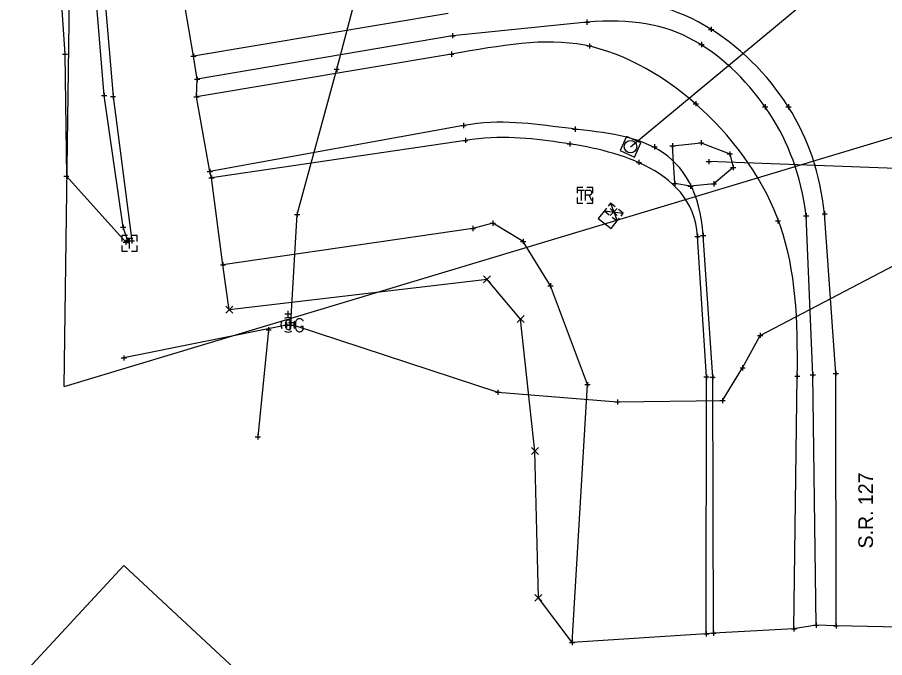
# Model space of a CAD drawing. Extents: x 1391912 to 1392597, y 304167 to 305226.
# Drawn here: x 1392156.2 to 1392322.5, y 304318.9 to 304441.7 of the extents above; entities that cross this region are included whole.
import ezdxf

# ---------------------------------------------------------------- set-up
doc = ezdxf.new("R2010")
doc.units = 0
for name, color, linetype in [('BD_X_Building', 7, 'Continuous'), ('DR_X_Erosion_Control', 7, 'Continuous'), ('DR_X_Storm_Sewer', 7, 'Continuous'), ('DV_X_Section_VMS_Line', 7, 'Continuous'), ('PM_X_Edge_Line', 7, 'Continuous'), ('PV_X_EOP', 7, 'Continuous'), ('PV_X_Shoulder_Aggregate', 7, 'Continuous'), ('RW_X_CL_100_Cardinal_Points', 7, 'Continuous'), ('RW_X_Esmt_SH', 7, 'Continuous'), ('SC_Scratch6', 7, 'Continuous'), ('SG_X_Controllers', 7, 'Continuous'), ('SG_X_Messenger_Wire', 7, 'Continuous'), ('SV_X_Break_Lines', 7, 'Continuous'), ('SV_X_Terrain_Boundary', 7, 'Continuous'), ('SV_X_Text', 7, 'Continuous'), ('SV_X_Toe_of_Slope', 7, 'Continuous'), ('SV_X_Top_of_Bank', 7, 'Continuous'), ('UT_X_FO', 7, 'Continuous'), ('UT_X_Gas', 7, 'Continuous'), ('UT_X_Gas_Cells', 7, 'Continuous'), ('UT_X_Overhead_Combined', 7, 'Continuous'), ('UT_X_Telecom_Cells', 7, 'Continuous')]:
    doc.layers.add(name, color=color, linetype=linetype)

msp = doc.modelspace()

# ---------------------------------------------------------------- linework, layer by layer
at = {"layer": 'BD_X_Building'}
for p, q in [((1392146.35, 304303.93), (1392176.61, 304336.54)), ((1392176.61, 304336.54), (1392223.75, 304292.79))]:
    msp.add_line(p, q, dxfattribs=at)
at = {"layer": 'DR_X_Erosion_Control'}
msp.add_lwpolyline([(1392281.81, 304417.04), (1392287.29, 304417.63), (1392292.82, 304415.47), (1392293.46, 304412.88), (1392289.75, 304409.75), (1392285.29, 304409.31), (1392282.24, 304409.83)], close=True, dxfattribs=at)
msp.add_lwpolyline([(1392281.81, 304417.04), (1392287.29, 304417.63), (1392292.82, 304415.47), (1392293.46, 304412.88), (1392289.75, 304409.75), (1392285.29, 304409.31), (1392282.24, 304409.83)], close=True, dxfattribs=at)
at = {"layer": 'DR_X_Storm_Sewer'}
msp.add_line((1392393.06, 304410.21), (1392288.79, 304414), dxfattribs=at)
at = {"layer": 'DV_X_Section_VMS_Line'}
for p, q in [((1392269.9, 304403.66), (1392271.23, 304405)), ((1392269.9, 304405), (1392271.23, 304403.66)), ((1392245.61, 304390.73), (1392246.94, 304392.07)), ((1392245.61, 304392.07), (1392246.94, 304390.73)), ((1392196.17, 304384.92), (1392197.5, 304386.26)), ((1392196.17, 304386.26), (1392197.5, 304384.92)), ((1392252.03, 304383.15), (1392253.37, 304384.49)), ((1392252.03, 304384.49), (1392253.37, 304383.15)), ((1392254.78, 304357.84), (1392256.11, 304359.18)), ((1392254.78, 304359.18), (1392256.11, 304357.84)), ((1392255.45, 304329.69), (1392256.78, 304331.02)), ((1392255.45, 304331.02), (1392256.78, 304329.69))]:
    msp.add_line(p, q, dxfattribs=at)
at = {"layer": 'PM_X_Edge_Line'}
for p, q in [((1392238.83, 304442.38), (1392189.99, 304434.24)), ((1392313.12, 304373.36), (1392310.98, 304404.01)), ((1392313.17, 304324.96), (1392313.12, 304373.36))]:
    msp.add_line(p, q, dxfattribs=at)
msp.add_open_spline([(1392310.98, 304404.01), (1392310.09, 304411.72), (1392305.75, 304424.92), (1392288.84, 304442.14), (1392274.13, 304445.52), (1392264.78, 304445.4)], degree=3, dxfattribs=at)
at = {"layer": 'PV_X_EOP'}
for p, q in [((1392265.4, 304440.73), (1392239.63, 304438.15)), ((1392239.63, 304438.15), (1392190.68, 304429.78)), ((1392308.72, 304373.11), (1392307.46, 304403.62)), ((1392309.33, 304325.11), (1392308.72, 304373.11))]:
    msp.add_line(p, q, dxfattribs=at)
msp.add_open_spline([(1392307.46, 304403.62), (1392306.37, 304411.58), (1392301.86, 304423.53), (1392286.65, 304439.27), (1392273.86, 304441.45), (1392265.4, 304440.73)], degree=3, dxfattribs=at)
at = {"layer": 'PV_X_Shoulder_Aggregate'}
for p, q in [((1392239.42, 304434.62), (1392190.55, 304426.44)), ((1392305.1, 304324.39), (1392305.74, 304372.84))]:
    msp.add_line(p, q, dxfattribs=at)
msp.add_open_spline([(1392305.74, 304372.84), (1392305.89, 304383.75), (1392305.02, 304402.43), (1392288.72, 304425.47), (1392264.99, 304439.43), (1392249.14, 304436.25), (1392239.42, 304434.62)], degree=3, dxfattribs=at)
at = {"layer": 'RW_X_CL_100_Cardinal_Points'}
msp.add_line((1392265.02, 304407.54), (1392265.02, 304407.54), dxfattribs=at)
for points in [[(1392264.62, 304409.04), (1392263.52, 304409.04), (1392263.52, 304407.94)], [(1392263.66, 304408.54), (1392264.91, 304408.54)], [(1392264.29, 304408.54), (1392264.29, 304406.54)], [(1392265.13, 304406.54), (1392265.13, 304408.54), (1392265.89, 304408.54), (1392265.97, 304408.53), (1392266.08, 304408.5), (1392266.12, 304408.46), (1392266.17, 304408.43), (1392266.24, 304408.35), (1392266.28, 304408.28), (1392266.31, 304408.15), (1392266.31, 304407.96), (1392266.3, 304407.9), (1392266.27, 304407.8), (1392266.2, 304407.69), (1392266.14, 304407.65), (1392266.09, 304407.61), (1392266.06, 304407.6), (1392266.01, 304407.58), (1392265.87, 304407.57), (1392265.13, 304407.57)], [(1392266.52, 304407.94), (1392266.52, 304409.04), (1392265.42, 304409.04)], [(1392263.52, 304407.14), (1392263.52, 304406.04), (1392264.62, 304406.04)], [(1392265.42, 304406.04), (1392266.52, 304406.04), (1392266.52, 304407.14)], [(1392265.87, 304407.57), (1392266.31, 304406.54)]]:
    msp.add_lwpolyline(points, dxfattribs=at)
at = {"layer": 'RW_X_Esmt_SH'}
for p, q in [((1392264.9, 304440.73), (1392265.9, 304440.73)), ((1392265.4, 304441.23), (1392265.4, 304440.23)), ((1392265.4, 304440.73), (1392265.4, 304440.73)), ((1392289.22, 304439.86), (1392289.22, 304438.86)), ((1392239.13, 304438.15), (1392240.13, 304438.15)), ((1392239.63, 304438.65), (1392239.63, 304437.65)), ((1392239.63, 304438.15), (1392239.63, 304438.15)), ((1392288.72, 304439.36), (1392289.72, 304439.36)), ((1392289.22, 304439.36), (1392289.22, 304439.36)), ((1392265.88, 304436.68), (1392265.88, 304435.68)), ((1392287.39, 304436.94), (1392287.39, 304435.94)), ((1392165.35, 304435.1), (1392165.35, 304434.1)), ((1392239.42, 304435.12), (1392239.42, 304434.12)), ((1392265.38, 304436.18), (1392266.38, 304436.18)), ((1392265.88, 304436.18), (1392265.88, 304436.18)), ((1392286.89, 304436.44), (1392287.89, 304436.44)), ((1392287.39, 304436.44), (1392287.39, 304436.44)), ((1392164.85, 304434.6), (1392165.85, 304434.6)), ((1392165.35, 304434.6), (1392165.35, 304434.6)), ((1392189.49, 304434.24), (1392190.49, 304434.24)), ((1392189.99, 304434.74), (1392189.99, 304433.74)), ((1392189.99, 304434.24), (1392189.99, 304434.24)), ((1392238.92, 304434.62), (1392239.92, 304434.62)), ((1392239.42, 304434.62), (1392239.42, 304434.62)), ((1392216.94, 304431.72), (1392217.94, 304431.72)), ((1392217.44, 304432.22), (1392217.44, 304431.22)), ((1392217.44, 304431.72), (1392217.44, 304431.72)), ((1392190.68, 304430.28), (1392190.68, 304429.28)), ((1392190.18, 304429.78), (1392191.18, 304429.78)), ((1392190.68, 304429.78), (1392190.68, 304429.78)), ((1392172.38, 304426.71), (1392173.38, 304426.71)), ((1392172.88, 304427.21), (1392172.88, 304426.21)), ((1392172.88, 304426.71), (1392172.88, 304426.71)), ((1392174.56, 304426.97), (1392174.56, 304425.97)), ((1392190.55, 304426.94), (1392190.55, 304425.94)), ((1392174.06, 304426.47), (1392175.06, 304426.47)), ((1392174.56, 304426.47), (1392174.56, 304426.47)), ((1392190.05, 304426.44), (1392191.05, 304426.44)), ((1392190.55, 304426.44), (1392190.55, 304426.44)), ((1392285.8, 304425.11), (1392286.8, 304425.11)), ((1392286.3, 304425.61), (1392286.3, 304424.61)), ((1392286.3, 304425.11), (1392286.3, 304425.11)), ((1392299.59, 304425.01), (1392299.59, 304424.01)), ((1392304.07, 304425), (1392304.07, 304424)), ((1392299.09, 304424.51), (1392300.09, 304424.51)), ((1392299.59, 304424.51), (1392299.59, 304424.51)), ((1392303.57, 304424.5), (1392304.57, 304424.5)), ((1392304.07, 304424.5), (1392304.07, 304424.5)), ((1392241.25, 304420.92), (1392242.25, 304420.92)), ((1392241.75, 304421.42), (1392241.75, 304420.42)), ((1392241.75, 304420.92), (1392241.75, 304420.92)), ((1392262.67, 304420.24), (1392263.67, 304420.24)), ((1392263.17, 304420.74), (1392263.17, 304419.74)), ((1392263.17, 304420.24), (1392263.17, 304420.24)), ((1392242.11, 304418.58), (1392242.11, 304417.58)), ((1392241.61, 304418.08), (1392242.61, 304418.08)), ((1392242.11, 304418.08), (1392242.11, 304418.08)), ((1392261.64, 304417.39), (1392262.64, 304417.39)), ((1392262.14, 304417.89), (1392262.14, 304416.89)), ((1392262.14, 304417.39), (1392262.14, 304417.39)), ((1392277.86, 304416.84), (1392278.86, 304416.84)), ((1392278.36, 304417.34), (1392278.36, 304416.34)), ((1392278.36, 304416.84), (1392278.36, 304416.84)), ((1392281.31, 304417.04), (1392282.31, 304417.04)), ((1392281.81, 304417.54), (1392281.81, 304416.54)), ((1392281.81, 304417.04), (1392281.81, 304417.04)), ((1392286.79, 304417.63), (1392287.79, 304417.63)), ((1392287.29, 304418.13), (1392287.29, 304417.13)), ((1392287.29, 304417.63), (1392287.29, 304417.63)), ((1392292.32, 304415.47), (1392293.32, 304415.47)), ((1392292.82, 304415.97), (1392292.82, 304414.97)), ((1392292.82, 304415.47), (1392292.82, 304415.47)), ((1392274.89, 304413.86), (1392275.89, 304413.86)), ((1392275.39, 304414.36), (1392275.39, 304413.36)), ((1392275.39, 304413.86), (1392275.39, 304413.86)), ((1392288.29, 304414), (1392289.29, 304414)), ((1392288.79, 304414.5), (1392288.79, 304413.5)), ((1392288.79, 304414), (1392288.79, 304414)), ((1392293.46, 304413.38), (1392293.46, 304412.38)), ((1392165.62, 304411.68), (1392165.62, 304410.68)), ((1392192.63, 304412.11), (1392193.63, 304412.11)), ((1392193.13, 304412.61), (1392193.13, 304411.61)), ((1392193.13, 304412.11), (1392193.13, 304412.11)), ((1392292.96, 304412.88), (1392293.96, 304412.88)), ((1392293.46, 304412.88), (1392293.46, 304412.88)), ((1392165.12, 304411.18), (1392166.12, 304411.18)), ((1392165.62, 304411.18), (1392165.62, 304411.18)), ((1392192.94, 304410.87), (1392193.94, 304410.87)), ((1392193.44, 304411.37), (1392193.44, 304410.37)), ((1392193.44, 304410.87), (1392193.44, 304410.87)), ((1392282.24, 304410.33), (1392282.24, 304409.33)), ((1392289.75, 304410.25), (1392289.75, 304409.25)), ((1392281.74, 304409.83), (1392282.74, 304409.83)), ((1392282.24, 304409.83), (1392282.24, 304409.83)), ((1392284.79, 304409.31), (1392285.79, 304409.31)), ((1392285.29, 304409.81), (1392285.29, 304408.81)), ((1392285.29, 304409.31), (1392285.29, 304409.31)), ((1392289.25, 304409.75), (1392290.25, 304409.75)), ((1392289.75, 304409.75), (1392289.75, 304409.75)), ((1392209.36, 304403.85), (1392210.36, 304403.85)), ((1392209.86, 304404.35), (1392209.86, 304403.35)), ((1392209.86, 304403.85), (1392209.86, 304403.85)), ((1392306.96, 304403.62), (1392307.96, 304403.62)), ((1392307.46, 304404.12), (1392307.46, 304403.12)), ((1392307.46, 304403.62), (1392307.46, 304403.62)), ((1392310.48, 304404.01), (1392311.48, 304404.01)), ((1392310.98, 304404.51), (1392310.98, 304403.51)), ((1392310.98, 304404.01), (1392310.98, 304404.01)), ((1392176.52, 304401.9), (1392176.52, 304400.9)), ((1392243.57, 304401.67), (1392243.57, 304400.67)), ((1392246.89, 304402.21), (1392247.89, 304402.21)), ((1392247.39, 304402.71), (1392247.39, 304401.71)), ((1392247.39, 304402.21), (1392247.39, 304402.21)), ((1392301.54, 304402.66), (1392302.54, 304402.66)), ((1392302.04, 304403.16), (1392302.04, 304402.16)), ((1392302.04, 304402.66), (1392302.04, 304402.66)), ((1392176.02, 304401.4), (1392177.02, 304401.4)), ((1392176.52, 304401.4), (1392176.52, 304401.4)), ((1392243.07, 304401.17), (1392244.07, 304401.17)), ((1392243.57, 304401.17), (1392243.57, 304401.17)), ((1392286.63, 304400.14), (1392286.63, 304399.14)), ((1392287.7, 304400.36), (1392287.7, 304399.36)), ((1392176.52, 304398.53), (1392177.52, 304398.53)), ((1392176.92, 304398.84), (1392177.92, 304398.84)), ((1392177.02, 304399.03), (1392177.02, 304398.03)), ((1392177.02, 304398.53), (1392177.02, 304398.53)), ((1392177.42, 304399.34), (1392177.42, 304398.34)), ((1392177.42, 304398.84), (1392177.42, 304398.84)), ((1392177.68, 304398.79), (1392178.68, 304398.79)), ((1392178.18, 304399.29), (1392178.18, 304398.29)), ((1392178.18, 304398.79), (1392178.18, 304398.79)), ((1392252.68, 304398.71), (1392253.68, 304398.71)), ((1392253.18, 304399.21), (1392253.18, 304398.21)), ((1392253.18, 304398.71), (1392253.18, 304398.71)), ((1392286.13, 304399.64), (1392287.13, 304399.64)), ((1392286.63, 304399.64), (1392286.63, 304399.64)), ((1392287.2, 304399.86), (1392288.2, 304399.86)), ((1392287.7, 304399.86), (1392287.7, 304399.86)), ((1392195.14, 304394.22), (1392196.14, 304394.22)), ((1392195.64, 304394.72), (1392195.64, 304393.72)), ((1392195.64, 304394.22), (1392195.64, 304394.22)), ((1392257.93, 304390.21), (1392258.93, 304390.21)), ((1392258.43, 304390.71), (1392258.43, 304389.71)), ((1392258.43, 304390.21), (1392258.43, 304390.21)), ((1392208.68, 304383.64), (1392208.68, 304382.64)), ((1392203.89, 304381.76), (1392204.89, 304381.76)), ((1392204.39, 304382.26), (1392204.39, 304381.26)), ((1392204.39, 304381.76), (1392204.39, 304381.76)), ((1392207.34, 304382.67), (1392208.34, 304382.67)), ((1392207.84, 304383.17), (1392207.84, 304382.17)), ((1392207.84, 304382.67), (1392207.84, 304382.67)), ((1392208.18, 304383.14), (1392209.18, 304383.14)), ((1392208.68, 304383.14), (1392208.68, 304383.14)), ((1392208.7, 304382.67), (1392209.7, 304382.67)), ((1392209.2, 304383.17), (1392209.2, 304382.17)), ((1392209.2, 304382.67), (1392209.2, 304382.67)), ((1392298.14, 304380.68), (1392299.14, 304380.68)), ((1392298.64, 304381.18), (1392298.64, 304380.18)), ((1392298.64, 304380.68), (1392298.64, 304380.68)), ((1392176.63, 304376.85), (1392176.63, 304375.85)), ((1392176.13, 304376.35), (1392177.13, 304376.35)), ((1392176.63, 304376.35), (1392176.63, 304376.35)), ((1392294.77, 304374.44), (1392295.77, 304374.44)), ((1392295.27, 304374.94), (1392295.27, 304373.94)), ((1392295.27, 304374.44), (1392295.27, 304374.44)), ((1392305.74, 304373.34), (1392305.74, 304372.34)), ((1392308.72, 304373.61), (1392308.72, 304372.61)), ((1392312.62, 304373.36), (1392313.62, 304373.36)), ((1392313.12, 304373.86), (1392313.12, 304372.86)), ((1392313.12, 304373.36), (1392313.12, 304373.36)), ((1392265.54, 304371.74), (1392265.54, 304370.74)), ((1392287.83, 304372.73), (1392288.83, 304372.73)), ((1392288.33, 304373.23), (1392288.33, 304372.23)), ((1392288.33, 304372.73), (1392288.33, 304372.73)), ((1392289.03, 304372.7), (1392290.03, 304372.7)), ((1392289.53, 304373.2), (1392289.53, 304372.2)), ((1392289.53, 304372.7), (1392289.53, 304372.7)), ((1392305.24, 304372.84), (1392306.24, 304372.84)), ((1392305.74, 304372.84), (1392305.74, 304372.84)), ((1392308.22, 304373.11), (1392309.22, 304373.11)), ((1392308.72, 304373.11), (1392308.72, 304373.11)), ((1392248.36, 304370.27), (1392248.36, 304369.27)), ((1392265.04, 304371.24), (1392266.04, 304371.24)), ((1392265.54, 304371.24), (1392265.54, 304371.24)), ((1392247.86, 304369.77), (1392248.86, 304369.77)), ((1392248.36, 304369.77), (1392248.36, 304369.77)), ((1392271.27, 304368.41), (1392271.27, 304367.41)), ((1392291.41, 304368.67), (1392291.41, 304367.67)), ((1392270.77, 304367.91), (1392271.77, 304367.91)), ((1392271.27, 304367.91), (1392271.27, 304367.91)), ((1392290.91, 304368.17), (1392291.91, 304368.17)), ((1392291.41, 304368.17), (1392291.41, 304368.17)), ((1392202.33, 304361.74), (1392202.33, 304360.74)), ((1392201.83, 304361.24), (1392202.83, 304361.24)), ((1392202.33, 304361.24), (1392202.33, 304361.24)), ((1392308.83, 304325.11), (1392309.83, 304325.11)), ((1392309.33, 304325.61), (1392309.33, 304324.61)), ((1392309.33, 304325.11), (1392309.33, 304325.11)), ((1392313.17, 304325.46), (1392313.17, 304324.46)), ((1392287.76, 304323.47), (1392288.76, 304323.47)), ((1392288.26, 304323.97), (1392288.26, 304322.97)), ((1392288.26, 304323.47), (1392288.26, 304323.47)), ((1392289.21, 304323.56), (1392290.21, 304323.56)), ((1392289.71, 304324.06), (1392289.71, 304323.06)), ((1392289.71, 304323.56), (1392289.71, 304323.56)), ((1392304.6, 304324.39), (1392305.6, 304324.39)), ((1392305.1, 304324.89), (1392305.1, 304323.89)), ((1392305.1, 304324.39), (1392305.1, 304324.39)), ((1392312.67, 304324.96), (1392313.67, 304324.96)), ((1392313.17, 304324.96), (1392313.17, 304324.96)), ((1392262.08, 304321.8), (1392263.08, 304321.8)), ((1392262.58, 304322.3), (1392262.58, 304321.3)), ((1392262.58, 304321.8), (1392262.58, 304321.8))]:
    msp.add_line(p, q, dxfattribs=at)
at = {"layer": 'SC_Scratch6'}
msp.add_lwpolyline([(1392271.78, 304416.11), (1392274.52, 304414.88), (1392275.75, 304417.61), (1392273.01, 304418.84)], close=True, dxfattribs=at)
msp.add_circle((1392273.77, 304416.86), 1.2, dxfattribs=at)
at = {"layer": 'SG_X_Controllers'}
for p, q in [((1392269.91, 304406.03), (1392271.22, 304402.63)), ((1392268.76, 304404.56), (1392272.37, 304404.1)), ((1392270.56, 304404.33), (1392270.56, 304404.33))]:
    msp.add_line(p, q, dxfattribs=at)
for points in [[(1392269.18, 304405.1), (1392268.76, 304404.56), (1392269.69, 304403.82)], [(1392270.85, 304405.3), (1392269.91, 304406.03), (1392269.49, 304405.49)], [(1392268.76, 304404.56), (1392267.6, 304403.08), (1392270.06, 304401.15), (1392271.22, 304402.63)], [(1392270.28, 304403.36), (1392271.22, 304402.63), (1392271.64, 304403.17)], [(1392271.95, 304403.56), (1392272.37, 304404.1), (1392271.44, 304404.84)]]:
    msp.add_lwpolyline(points, dxfattribs=at)
at = {"layer": 'SG_X_Messenger_Wire'}
msp.add_line((1392273.77, 304416.86), (1392307.57, 304444.87), dxfattribs=at)
at = {"layer": 'SV_X_Break_Lines'}
for p, q in [((1392242.11, 304418.08), (1392193.44, 304410.87)), ((1392288.33, 304372.73), (1392286.63, 304399.64)), ((1392288.26, 304323.47), (1392288.33, 304372.73))]:
    msp.add_line(p, q, dxfattribs=at)
msp.add_open_spline([(1392286.63, 304399.64), (1392286.19, 304406.66), (1392277.07, 304414.7), (1392260.1, 304417.96), (1392248.88, 304419.08), (1392242.11, 304418.08)], degree=3, dxfattribs=at)
at = {"layer": 'SV_X_Terrain_Boundary'}
msp.add_lwpolyline([(1392325.19, 304324.71), (1392313.17, 304324.96), (1392309.33, 304325.11), (1392305.1, 304324.39), (1392289.71, 304323.56), (1392288.26, 304323.47), (1392262.58, 304321.8), (1392256.12, 304330.36), (1392255.45, 304358.51), (1392252.7, 304383.82), (1392246.27, 304391.4), (1392196.84, 304385.59), (1392195.64, 304394.22), (1392193.44, 304410.87), (1392193.13, 304412.11), (1392190.55, 304426.44), (1392190.68, 304429.78), (1392189.99, 304434.24), (1392187.94, 304446.23)], dxfattribs=at)
at = {"layer": 'SV_X_Toe_of_Slope'}
for p, q in [((1392241.75, 304420.92), (1392193.13, 304412.11)), ((1392289.53, 304372.7), (1392287.7, 304399.86)), ((1392289.71, 304323.56), (1392289.53, 304372.7))]:
    msp.add_line(p, q, dxfattribs=at)
msp.add_open_spline([(1392287.7, 304399.86), (1392287.15, 304407.97), (1392280.96, 304418.66), (1392260.86, 304420.23), (1392248.89, 304422.22), (1392241.75, 304420.92)], degree=3, dxfattribs=at)
at = {"layer": 'SV_X_Top_of_Bank'}
msp.add_lwpolyline([(1392262.58, 304321.8), (1392265.54, 304371.24), (1392258.43, 304390.21), (1392253.18, 304398.71), (1392247.39, 304402.21), (1392243.57, 304401.17), (1392195.64, 304394.22)], dxfattribs=at)
at = {"layer": 'UT_X_FO'}
for points in [[(1392177.42, 304398.84), (1392176.52, 304401.4), (1392172.88, 304426.71), (1392170.2, 304459.35), (1392169.81, 304490.44), (1392170.07, 304506.42), (1392170.44, 304523.54)], [(1392171.84, 304523.46), (1392171.79, 304505.68), (1392171.59, 304489.53), (1392171.76, 304470.32), (1392171.75, 304459.61), (1392174.56, 304426.47), (1392178.18, 304398.79)], [(1392160.88, 304504.2), (1392161.41, 304487.63), (1392163.22, 304465.88), (1392165.35, 304434.6), (1392165.62, 304411.18), (1392177.02, 304398.53)]]:
    msp.add_lwpolyline(points, dxfattribs=at)
at = {"layer": 'UT_X_Gas'}
for points in [[(1392208.68, 304383.14), (1392209.86, 304403.85), (1392217.44, 304431.72), (1392228.1, 304472.01), (1392237.57, 304508.48), (1392247.36, 304543.76), (1392255.82, 304577.61)], [(1392209.2, 304382.67), (1392248.36, 304369.77), (1392271.27, 304367.91), (1392291.41, 304368.17), (1392295.27, 304374.44), (1392298.64, 304380.68), (1392367.72, 304416.84), (1392378.76, 304440.92), (1392400.63, 304449.06), (1392408.05, 304456.92), (1392440.45, 304472.3), (1392459.13, 304475.15), (1392487.25, 304485.31), (1392492.6, 304487.47)], [(1392207.84, 304382.67), (1392176.63, 304376.35)], [(1392204.39, 304381.76), (1392202.33, 304361.24)]]:
    msp.add_lwpolyline(points, dxfattribs=at)
at = {"layer": 'UT_X_Gas_Cells'}
for p, q in [((1392208.15, 304384.12), (1392208.15, 304385.39)), ((1392208.79, 304384.76), (1392207.52, 304384.76)), ((1392208.53, 304381.63), (1392208.53, 304383.63)), ((1392208.53, 304382.63), (1392207.58, 304382.63)), ((1392208.15, 304382.72), (1392208.15, 304382.72))]:
    msp.add_line(p, q, dxfattribs=at)
for points in [[(1392208.68, 304383.27), (1392208.67, 304383.34), (1392208.63, 304383.41), (1392208.56, 304383.48), (1392208.46, 304383.57), (1392208.39, 304383.59), (1392208.33, 304383.61), (1392208.25, 304383.62), (1392208.07, 304383.62), (1392208, 304383.61), (1392207.96, 304383.59), (1392207.9, 304383.57), (1392207.79, 304383.48), (1392207.72, 304383.38), (1392207.68, 304383.27), (1392207.65, 304383.11), (1392207.62, 304382.89), (1392207.62, 304382.59), (1392207.64, 304382.35), (1392207.69, 304382.16), (1392207.78, 304381.99), (1392207.85, 304381.94), (1392207.93, 304381.88), (1392208.09, 304381.82), (1392208.25, 304381.82), (1392208.4, 304381.85), (1392208.46, 304381.88), (1392208.51, 304381.91), (1392208.57, 304381.97), (1392208.63, 304382.05), (1392208.68, 304382.18), (1392208.68, 304382.53), (1392208.39, 304382.53)], [(1392211.01, 304383.39), (1392210.99, 304383.48), (1392210.93, 304383.58), (1392210.83, 304383.68), (1392210.69, 304383.8), (1392210.59, 304383.84), (1392210.52, 304383.86), (1392210.4, 304383.88), (1392210.16, 304383.88), (1392210.06, 304383.86), (1392210, 304383.84), (1392209.93, 304383.8), (1392209.77, 304383.68), (1392209.67, 304383.54), (1392209.61, 304383.39), (1392209.57, 304383.17), (1392209.53, 304382.85), (1392209.53, 304382.44), (1392209.55, 304382.11), (1392209.63, 304381.85), (1392209.75, 304381.61), (1392209.85, 304381.54), (1392209.96, 304381.46), (1392210.18, 304381.38), (1392210.4, 304381.38), (1392210.61, 304381.42), (1392210.69, 304381.46), (1392210.77, 304381.5), (1392210.85, 304381.57), (1392210.93, 304381.69), (1392211.01, 304381.87), (1392211.01, 304382.36), (1392210.59, 304382.36)]]:
    msp.add_lwpolyline(points, dxfattribs=at)
for start, end in [(150.0184, 209.9816), (60.0184, 120.0157), (330.0184, 29.9816), (239.9843, 299.9816)]:
    msp.add_arc((1392208.15, 304382.72), 1.4, start, end, dxfattribs=at)
at = {"layer": 'UT_X_Overhead_Combined'}
for q in [(1392167.24, 304517.47), (1392586.59, 304497.87)]:
    msp.add_line((1392165.2, 304370.85), q, dxfattribs=at)
at = {"layer": 'UT_X_Telecom_Cells'}
for p, q in [((1392177.07, 304399.31), (1392178.37, 304399.31)), ((1392177.72, 304397.31), (1392177.72, 304399.31)), ((1392177.72, 304398.31), (1392177.72, 304398.31))]:
    msp.add_line(p, q, dxfattribs=at)
for points in [[(1392177.32, 304399.81), (1392176.22, 304399.81), (1392176.22, 304398.71)], [(1392179.22, 304398.71), (1392179.22, 304399.81), (1392178.12, 304399.81)], [(1392176.22, 304397.91), (1392176.22, 304396.81), (1392177.32, 304396.81)], [(1392178.12, 304396.81), (1392179.22, 304396.81), (1392179.22, 304397.91)]]:
    msp.add_lwpolyline(points, dxfattribs=at)

# ---------------------------------------------------------------- texts
at = {"layer": 'SV_X_Text'}
msp.add_text('S.R. 127', height=2.8, rotation=90, dxfattribs=at).set_placement((1392320.25, 304339.82))

doc.saveas('drawing.dxf')
